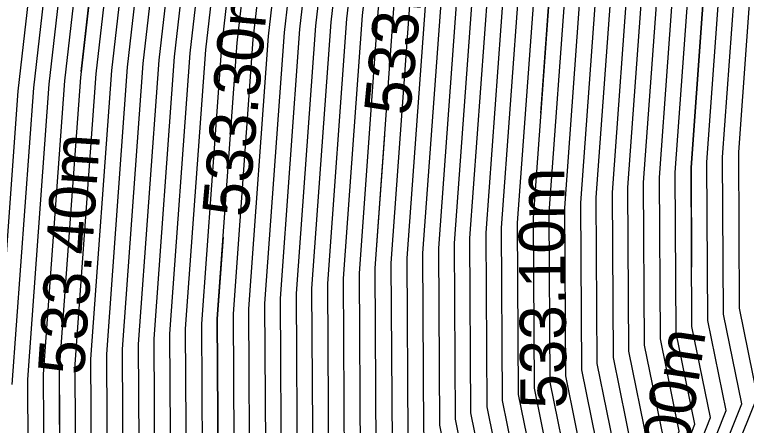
# Model space of a CAD drawing. Extents: x -866683 to -866410, y -1041951 to -1040252.
# Drawn here: x -866449.115 to -866444.371, y -1041933.595 to -1041930.934 of the extents above; entities that cross this region are included whole.
import ezdxf

# ---------------------------------------------------------------- set-up
doc = ezdxf.new("R2010")
doc.units = 0
for name, color, linetype in [('V-HL', 7, 'Continuous'), ('V-VEDL', 7, 'Continuous'), ('V_po_cm', 7, 'Continuous')]:
    doc.layers.add(name, color=color, linetype=linetype)

msp = doc.modelspace()

# ---------------------------------------------------------------- linework, layer by layer
at = {"layer": 'V-HL'}
msp.add_lwpolyline([(-866444.9217, -1041934.3497), (-866444.6048, -1041933.5435), (-866444.724, -1041932.9551), (-866444.7301, -1041931.9234), (-866444.6231, -1041930.4482), (-866444.4031, -1041928.5297), (-866444.4224, -1041928.4411)], dxfattribs=at)
at = {"layer": 'V-VEDL'}
for points in [[(-866449.7169, -1041924.4172), (-866449.1108, -1041924.2576), (-866448.5043, -1041924.4695), (-866447.5946, -1041924.9732), (-866446.3815, -1041925.7685), (-866445.6512, -1041926.9834), (-866445.4039, -1041928.6176), (-866445.6394, -1041930.6714), (-866445.7539, -1041932.2504), (-866445.7474, -1041933.3549), (-866445.6198, -1041933.9847), (-866446.0907, -1041935.3297), (-866447.16, -1041937.39), (-866450.4954, -1041942.9408)], [(-866450.4284, -1041941.6368), (-866447.8087, -1041937.2771), (-866446.9808, -1041935.6001), (-866446.6348, -1041934.426), (-866446.7708, -1041933.7547), (-866446.7777, -1041932.5775), (-866446.6557, -1041930.8945), (-866446.4047, -1041928.7056), (-866446.5506, -1041927.0409), (-866447.0935, -1041925.9004), (-866448.0334, -1041925.2842), (-866448.7383, -1041924.894), (-866449.2081, -1041924.7298), (-866449.6778, -1041924.8534)], [(-866450.3613, -1041940.3327), (-866448.4574, -1041937.1642), (-866447.8709, -1041935.8705), (-866447.6498, -1041934.8672), (-866447.7942, -1041934.1545), (-866447.8016, -1041932.9046), (-866447.672, -1041931.1176), (-866447.4055, -1041928.7935), (-866447.45, -1041927.0984), (-866447.8056, -1041926.0323), (-866448.4722, -1041925.5952), (-866448.9722, -1041925.3184), (-866449.3055, -1041925.2019), (-866449.6386, -1041925.2896)], [(-866449.5994, -1041925.7259), (-866449.4028, -1041925.6741), (-866449.2061, -1041925.7428), (-866448.9111, -1041925.9062), (-866448.5176, -1041926.1641), (-866448.3494, -1041927.1559), (-866448.4062, -1041928.8814), (-866448.6883, -1041931.3407), (-866448.8254, -1041933.2317), (-866448.8176, -1041934.5543), (-866448.6648, -1041935.3085), (-866448.761, -1041936.1408), (-866449.1061, -1041937.0514), (-866450.2943, -1041939.0287)]]:
    msp.add_lwpolyline(points, dxfattribs=at)
at = {"layer": 'V_po_cm'}
for points in [[(-866449.376, -1041923.747), (-866448.9842, -1041923.6438), (-866448.2002, -1041923.9178), (-866447.0241, -1041924.5689), (-866445.4558, -1041925.5971), (-866444.4821, -1041926.9086), (-866444.1029, -1041928.5033), (-866444.3182, -1041930.3813), (-866444.4229, -1041931.8252), (-866444.417, -1041932.8352), (-866444.3003, -1041933.4111), (-866444.9335, -1041934.9782), (-866446.3166, -1041937.5367), (-866448.4496, -1041941.0864), (-866449.9198, -1041942.6695)], [(-866449.9242, -1041942.5721), (-866448.4787, -1041941.0155), (-866446.3815, -1041937.5254), (-866445.0226, -1041935.0053), (-866444.4018, -1041933.4552), (-866444.5193, -1041932.8751), (-866444.5253, -1041931.8579), (-866444.4199, -1041930.4036), (-866444.203, -1041928.5121), (-866444.572, -1041926.9143), (-866445.527, -1041925.6103), (-866447.068, -1041924.6), (-866448.2236, -1041923.9602), (-866448.9939, -1041923.691), (-866449.379, -1041923.7924)], [(-866449.9286, -1041942.4747), (-866448.5078, -1041940.9447), (-866446.4464, -1041937.5141), (-866445.1116, -1041935.0323), (-866444.5033, -1041933.4993), (-866444.6216, -1041932.9151), (-866444.6277, -1041931.8906), (-866444.5215, -1041930.4259), (-866444.303, -1041928.5209), (-866444.6619, -1041926.9201), (-866445.5982, -1041925.6235), (-866447.1119, -1041924.6311), (-866448.247, -1041924.0027), (-866449.0037, -1041923.7382), (-866449.3819, -1041923.8378)], [(-866449.9375, -1041942.2799), (-866448.5659, -1041940.803), (-866446.5761, -1041937.4915), (-866445.2896, -1041935.0864), (-866444.7063, -1041933.5876), (-866444.8263, -1041932.9951), (-866444.8325, -1041931.9561), (-866444.7248, -1041930.4705), (-866444.5032, -1041928.5385), (-866444.8418, -1041926.9316), (-866445.7406, -1041925.6499), (-866447.1996, -1041924.6933), (-866448.2938, -1041924.0876), (-866449.0232, -1041923.8327), (-866449.3877, -1041923.9286)], [(-866449.9419, -1041942.1825), (-866448.595, -1041940.7321), (-866446.641, -1041937.4802), (-866445.3786, -1041935.1134), (-866444.8078, -1041933.6317), (-866444.9287, -1041933.0351), (-866444.9349, -1041931.9888), (-866444.8264, -1041930.4929), (-866444.6033, -1041928.5473), (-866444.9317, -1041926.9374), (-866445.8118, -1041925.6631), (-866447.2435, -1041924.7244), (-866448.3172, -1041924.13), (-866449.0329, -1041923.8799), (-866449.3906, -1041923.9741)], [(-866449.9463, -1041942.0851), (-866448.6241, -1041940.6613), (-866446.7059, -1041937.469), (-866445.4676, -1041935.1405), (-866444.9093, -1041933.6758), (-866445.031, -1041933.075), (-866445.0372, -1041932.0215), (-866444.928, -1041930.5152), (-866444.7033, -1041928.5561), (-866445.0217, -1041926.9431), (-866445.883, -1041925.6762), (-866447.2874, -1041924.7555), (-866448.3406, -1041924.1724), (-866449.0426, -1041923.9271), (-866449.3935, -1041924.0195)], [(-866449.9507, -1041941.9877), (-866448.6532, -1041940.5905), (-866446.7707, -1041937.4577), (-866445.5566, -1041935.1675), (-866445.0108, -1041933.72), (-866445.1333, -1041933.115), (-866445.1396, -1041932.0542), (-866445.0297, -1041930.5375), (-866444.8034, -1041928.5649), (-866445.1116, -1041926.9489), (-866445.9542, -1041925.6894), (-866447.3313, -1041924.7866), (-866448.364, -1041924.2149), (-866449.0524, -1041923.9743), (-866449.3964, -1041924.0649)], [(-866449.3993, -1041924.1103), (-866449.0621, -1041924.0215), (-866448.3874, -1041924.2573), (-866447.3752, -1041924.8177), (-866446.0254, -1041925.7026), (-866445.2016, -1041926.9546), (-866444.9035, -1041928.5737), (-866445.1313, -1041930.5598), (-866445.242, -1041932.0869), (-866445.2357, -1041933.155), (-866445.1123, -1041933.7641), (-866445.6456, -1041935.1945), (-866446.8356, -1041937.4464), (-866448.6823, -1041940.5196), (-866449.9551, -1041941.8903)], [(-866449.9596, -1041941.7928), (-866448.7114, -1041940.4488), (-866446.9005, -1041937.4351), (-866445.7346, -1041935.2216), (-866445.2138, -1041933.8082), (-866445.338, -1041933.195), (-866445.3444, -1041932.1196), (-866445.2329, -1041930.5821), (-866445.0036, -1041928.5825), (-866445.2915, -1041926.9604), (-866446.0966, -1041925.7158), (-866447.419, -1041924.8488), (-866448.4108, -1041924.2998), (-866449.0718, -1041924.0688), (-866449.4022, -1041924.1557)], [(-866449.4051, -1041924.2012), (-866449.0816, -1041924.116), (-866448.4342, -1041924.3422), (-866447.4629, -1041924.8799), (-866446.1679, -1041925.729), (-866445.3814, -1041926.9661), (-866445.1037, -1041928.5912), (-866445.3345, -1041930.6044), (-866445.4468, -1041932.1523), (-866445.4404, -1041933.235), (-866445.3153, -1041933.8523), (-866445.8236, -1041935.2486), (-866446.9654, -1041937.4238), (-866448.7404, -1041940.3779), (-866449.964, -1041941.6954)], [(-866449.4109, -1041924.292), (-866449.101, -1041924.2104), (-866448.4809, -1041924.4271), (-866447.5507, -1041924.9421), (-866446.3103, -1041925.7554), (-866445.5613, -1041926.9776), (-866445.3038, -1041928.6088), (-866445.5378, -1041930.649), (-866445.6515, -1041932.2177), (-866445.645, -1041933.3149), (-866445.5183, -1041933.9406), (-866446.0017, -1041935.3027), (-866447.0951, -1041937.4012), (-866448.7986, -1041940.2362), (-866449.9728, -1041941.5006)], [(-866449.9684, -1041941.598), (-866448.7695, -1041940.3071), (-866447.0302, -1041937.4125), (-866445.9127, -1041935.2757), (-866445.4168, -1041933.8965), (-866445.5427, -1041933.2749), (-866445.5492, -1041932.185), (-866445.4362, -1041930.6267), (-866445.2037, -1041928.6), (-866445.4714, -1041926.9719), (-866446.2391, -1041925.7422), (-866447.5068, -1041924.911), (-866448.4576, -1041924.3847), (-866449.0913, -1041924.1632), (-866449.408, -1041924.2466)], [(-866449.1205, -1041924.3048), (-866448.5277, -1041924.512), (-866447.6385, -1041925.0043), (-866446.4527, -1041925.7817), (-866445.7412, -1041926.9891), (-866445.504, -1041928.6264), (-866445.7411, -1041930.6937), (-866445.8563, -1041932.2832), (-866445.8497, -1041933.3949), (-866445.7213, -1041934.0288), (-866446.1797, -1041935.3568), (-866447.2248, -1041937.3787), (-866448.8568, -1041940.0945), (-866449.9816, -1041941.3058)], [(-866449.9861, -1041941.2084), (-866448.8859, -1041940.0237), (-866447.2897, -1041937.3674), (-866446.2687, -1041935.3838), (-866445.8228, -1041934.073), (-866445.9521, -1041933.4349), (-866445.9587, -1041932.3159), (-866445.8427, -1041930.716), (-866445.6041, -1041928.6352), (-866445.8311, -1041926.9949), (-866446.5239, -1041925.7949), (-866447.6823, -1041925.0354), (-866448.5511, -1041924.5544), (-866449.1302, -1041924.352)], [(-866449.14, -1041924.3993), (-866448.5745, -1041924.5969), (-866447.7262, -1041925.0665), (-866446.5951, -1041925.8081), (-866445.9211, -1041927.0006), (-866445.7041, -1041928.644), (-866445.9443, -1041930.7383), (-866446.0611, -1041932.3486), (-866446.0544, -1041933.4748), (-866445.9243, -1041934.1171), (-866446.3577, -1041935.4108), (-866447.3546, -1041937.3561), (-866448.9149, -1041939.9529), (-866449.9905, -1041941.111)], [(-866449.9949, -1041941.0136), (-866448.944, -1041939.882), (-866447.4195, -1041937.3448), (-866446.4467, -1041935.4379), (-866446.0258, -1041934.1612), (-866446.1567, -1041933.5148), (-866446.1634, -1041932.3813), (-866446.0459, -1041930.7606), (-866445.8042, -1041928.6528), (-866446.011, -1041927.0064), (-866446.6663, -1041925.8213), (-866447.7701, -1041925.0976), (-866448.5979, -1041924.6393), (-866449.1497, -1041924.4465)], [(-866449.1594, -1041924.4937), (-866448.6213, -1041924.6818), (-866447.814, -1041925.1287), (-866446.7375, -1041925.8345), (-866446.1009, -1041927.0121), (-866445.9043, -1041928.6616), (-866446.1476, -1041930.7829), (-866446.2658, -1041932.414), (-866446.2591, -1041933.5548), (-866446.1273, -1041934.2053), (-866446.5357, -1041935.4649), (-866447.4843, -1041937.3335), (-866448.9731, -1041939.8112), (-866449.9993, -1041940.9162)], [(-866449.1692, -1041924.5409), (-866448.6447, -1041924.7242), (-866447.8579, -1041925.1598), (-866446.8087, -1041925.8477), (-866446.1909, -1041927.0179), (-866446.0044, -1041928.6704), (-866446.2492, -1041930.8052), (-866446.3682, -1041932.4467), (-866446.3614, -1041933.5948), (-866446.2288, -1041934.2495), (-866446.6247, -1041935.492), (-866447.5492, -1041937.3222), (-866449.0022, -1041939.7403), (-866450.0037, -1041940.8188)], [(-866449.1789, -1041924.5881), (-866448.6681, -1041924.7666), (-866447.9018, -1041925.1909), (-866446.8799, -1041925.8608), (-866446.2808, -1041927.0236), (-866446.1044, -1041928.6792), (-866446.3508, -1041930.8275), (-866446.4706, -1041932.4794), (-866446.4638, -1041933.6348), (-866446.3303, -1041934.2936), (-866446.7138, -1041935.519), (-866447.6141, -1041937.3109), (-866449.0313, -1041939.6695), (-866450.0081, -1041940.7214)], [(-866449.1886, -1041924.6353), (-866448.6915, -1041924.8091), (-866447.9456, -1041925.222), (-866446.9511, -1041925.874), (-866446.3707, -1041927.0294), (-866446.2045, -1041928.688), (-866446.4525, -1041930.8499), (-866446.573, -1041932.5121), (-866446.5661, -1041933.6747), (-866446.4318, -1041934.3377), (-866446.8028, -1041935.546), (-866447.6789, -1041937.2997), (-866449.0604, -1041939.5986), (-866450.0125, -1041940.6239)], [(-866449.1984, -1041924.6826), (-866448.7149, -1041924.8515), (-866447.9895, -1041925.2531), (-866447.0223, -1041925.8872), (-866446.4607, -1041927.0351), (-866446.3046, -1041928.6968), (-866446.5541, -1041930.8722), (-866446.6754, -1041932.5448), (-866446.6684, -1041933.7147), (-866446.5333, -1041934.3818), (-866446.8918, -1041935.5731), (-866447.7438, -1041937.2884), (-866449.0895, -1041939.5278), (-866450.017, -1041940.5265)], [(-866449.1476, -1041939.3861), (-866447.8736, -1041937.2658), (-866447.0698, -1041935.6271), (-866446.7363, -1041934.4701), (-866446.8731, -1041933.7947), (-866446.8801, -1041932.6102), (-866446.7573, -1041930.9168), (-866446.5048, -1041928.7143), (-866446.6406, -1041927.0466), (-866447.1647, -1041925.9136), (-866448.0773, -1041925.3153), (-866448.7617, -1041924.9364), (-866449.2179, -1041924.777)], [(-866449.1767, -1041939.3152), (-866447.9384, -1041937.2545), (-866447.1588, -1041935.6542), (-866446.8378, -1041934.5142), (-866446.9755, -1041933.8347), (-866446.9825, -1041932.6429), (-866446.859, -1041930.9391), (-866446.6048, -1041928.7231), (-866446.7305, -1041927.0524), (-866447.2359, -1041925.9268), (-866448.1212, -1041925.3464), (-866448.7851, -1041924.9789), (-866449.2276, -1041924.8242)], [(-866449.2058, -1041939.2444), (-866448.0033, -1041937.2432), (-866447.2478, -1041935.6812), (-866446.9393, -1041934.5583), (-866447.0778, -1041933.8746), (-866447.0849, -1041932.6757), (-866446.9606, -1041930.9614), (-866446.7049, -1041928.7319), (-866446.8204, -1041927.0581), (-866447.3071, -1041925.94), (-866448.1651, -1041925.3775), (-866448.8085, -1041925.0213), (-866449.2373, -1041924.8714)], [(-866449.2349, -1041939.1736), (-866448.0682, -1041937.2319), (-866447.3368, -1041935.7082), (-866447.0408, -1041934.6025), (-866447.1801, -1041933.9146), (-866447.1873, -1041932.7084), (-866447.0622, -1041930.9837), (-866446.805, -1041928.7407), (-866446.9104, -1041927.0639), (-866447.3783, -1041925.9531), (-866448.2089, -1041925.4086), (-866448.8318, -1041925.0637), (-866449.2471, -1041924.9186)], [(-866449.2568, -1041924.9659), (-866448.8552, -1041925.1062), (-866448.2528, -1041925.4397), (-866447.4496, -1041925.9663), (-866447.0003, -1041927.0696), (-866446.9051, -1041928.7495), (-866447.1639, -1041931.0061), (-866447.2897, -1041932.7411), (-866447.2825, -1041933.9546), (-866447.1423, -1041934.6466), (-866447.4258, -1041935.7353), (-866448.133, -1041937.2207), (-866449.264, -1041939.1027)], [(-866449.293, -1041939.0319), (-866448.1979, -1041937.2094), (-866447.5148, -1041935.7623), (-866447.2438, -1041934.6907), (-866447.3848, -1041933.9946), (-866447.392, -1041932.7738), (-866447.2655, -1041931.0284), (-866447.0051, -1041928.7583), (-866447.0902, -1041927.0754), (-866447.5208, -1041925.9795), (-866448.2967, -1041925.4708), (-866448.8786, -1041925.1486), (-866449.2665, -1041925.0131)], [(-866449.2763, -1041925.0603), (-866448.902, -1041925.1911), (-866448.3406, -1041925.5019), (-866447.592, -1041925.9927), (-866447.1802, -1041927.0811), (-866447.1052, -1041928.7671), (-866447.3671, -1041931.0507), (-866447.4944, -1041932.8065), (-866447.4872, -1041934.0345), (-866447.3453, -1041934.7348), (-866447.6039, -1041935.7894), (-866448.2628, -1041937.1981), (-866449.3221, -1041938.961)], [(-866449.3512, -1041938.8902), (-866448.3277, -1041937.1868), (-866447.6929, -1041935.8164), (-866447.4468, -1041934.779), (-866447.5895, -1041934.0745), (-866447.5968, -1041932.8392), (-866447.4687, -1041931.073), (-866447.2053, -1041928.7759), (-866447.2701, -1041927.0869), (-866447.6632, -1041926.0059), (-866448.3845, -1041925.533), (-866448.9254, -1041925.2335), (-866449.286, -1041925.1075)], [(-866449.2957, -1041925.1547), (-866448.9488, -1041925.276), (-866448.4284, -1041925.5641), (-866447.7344, -1041926.0191), (-866447.3601, -1041927.0926), (-866447.3054, -1041928.7847), (-866447.5704, -1041931.0953), (-866447.6992, -1041932.8719), (-866447.6918, -1041934.1145), (-866447.5483, -1041934.8231), (-866447.7819, -1041935.8434), (-866448.3925, -1041937.1755), (-866449.3803, -1041938.8193)], [(-866449.3152, -1041925.2491), (-866448.9956, -1041925.3608), (-866448.5161, -1041925.6263), (-866447.8768, -1041926.0454), (-866447.5399, -1041927.1041), (-866447.5055, -1041928.8023), (-866447.7736, -1041931.1399), (-866447.904, -1041932.9373), (-866447.8965, -1041934.1945), (-866447.7513, -1041934.9114), (-866447.9599, -1041935.8975), (-866448.5223, -1041937.1529), (-866449.4385, -1041938.6776)], [(-866449.4675, -1041938.6068), (-866448.5872, -1041937.1417), (-866448.0489, -1041935.9245), (-866447.8528, -1041934.9555), (-866447.9989, -1041934.2344), (-866448.0063, -1041932.97), (-866447.8753, -1041931.1622), (-866447.6056, -1041928.8111), (-866447.6299, -1041927.1099), (-866447.948, -1041926.0586), (-866448.56, -1041925.6574), (-866449.019, -1041925.4033), (-866449.3249, -1041925.2964)], [(-866449.4966, -1041938.5359), (-866448.652, -1041937.1304), (-866448.1379, -1041935.9516), (-866447.9543, -1041934.9996), (-866448.1012, -1041934.2744), (-866448.1087, -1041933.0027), (-866447.9769, -1041931.1846), (-866447.7057, -1041928.8199), (-866447.7198, -1041927.1156), (-866448.0192, -1041926.0718), (-866448.6039, -1041925.6885), (-866449.0424, -1041925.4457), (-866449.3347, -1041925.3436)], [(-866449.5257, -1041938.4651), (-866448.7169, -1041937.1191), (-866448.2269, -1041935.9786), (-866448.0558, -1041935.0437), (-866448.2035, -1041934.3144), (-866448.2111, -1041933.0355), (-866448.0785, -1041931.2069), (-866447.8058, -1041928.8287), (-866447.8097, -1041927.1214), (-866448.0904, -1041926.085), (-866448.6478, -1041925.7196), (-866449.0658, -1041925.4882), (-866449.3444, -1041925.3908)], [(-866449.3541, -1041925.438), (-866449.0892, -1041925.5306), (-866448.6917, -1041925.7507), (-866448.1616, -1041926.0982), (-866447.8997, -1041927.1271), (-866447.9059, -1041928.8374), (-866448.1801, -1041931.2292), (-866448.3135, -1041933.0682), (-866448.3059, -1041934.3544), (-866448.1573, -1041935.0879), (-866448.3159, -1041936.0057), (-866448.7818, -1041937.1078), (-866449.5548, -1041938.3943)], [(-866449.5839, -1041938.3234), (-866448.8466, -1041937.0965), (-866448.405, -1041936.0327), (-866448.2588, -1041935.132), (-866448.4082, -1041934.3944), (-866448.4159, -1041933.1009), (-866448.2818, -1041931.2515), (-866448.0059, -1041928.8462), (-866447.9896, -1041927.1329), (-866448.2328, -1041926.1114), (-866448.7355, -1041925.7818), (-866449.1126, -1041925.5731), (-866449.3639, -1041925.4852)], [(-866449.613, -1041938.2526), (-866448.9115, -1041937.0852), (-866448.494, -1041936.0597), (-866448.3603, -1041935.1761), (-866448.5106, -1041934.4343), (-866448.5183, -1041933.1336), (-866448.3834, -1041931.2738), (-866448.106, -1041928.855), (-866448.0795, -1041927.1386), (-866448.304, -1041926.1246), (-866448.7794, -1041925.8129), (-866449.136, -1041925.6155)], [(-866449.642, -1041938.1817), (-866448.9764, -1041937.0739), (-866448.583, -1041936.0868), (-866448.4618, -1041935.2202), (-866448.6129, -1041934.4743), (-866448.6206, -1041933.1663), (-866448.485, -1041931.2961), (-866448.2061, -1041928.8638), (-866448.1695, -1041927.1444), (-866448.3752, -1041926.1377), (-866448.8233, -1041925.844), (-866449.1594, -1041925.6579)], [(-866449.6711, -1041938.1109), (-866449.0413, -1041937.0626), (-866448.672, -1041936.1138), (-866448.5633, -1041935.2644), (-866448.7152, -1041934.5143), (-866448.723, -1041933.199), (-866448.5867, -1041931.3184), (-866448.3062, -1041928.8726), (-866448.2594, -1041927.1501), (-866448.4464, -1041926.1509), (-866448.8672, -1041925.8751), (-866449.1827, -1041925.7004)], [(-866449.171, -1041937.0401), (-866448.85, -1041936.1679), (-866448.7663, -1041935.3526), (-866448.9199, -1041934.5943), (-866448.9278, -1041933.2644), (-866448.7899, -1041931.3631), (-866448.5063, -1041928.8902), (-866448.4393, -1041927.1616), (-866448.5888, -1041926.1773), (-866448.955, -1041925.9373), (-866449.2295, -1041925.7853)], [(-866449.2763, -1041925.8702), (-866449.0427, -1041925.9995), (-866448.7313, -1041926.2037), (-866448.6192, -1041927.1731), (-866448.7065, -1041928.9078), (-866448.9932, -1041931.4077), (-866449.1325, -1041933.3298)], [(-866449.2359, -1041937.0288), (-866448.939, -1041936.1949), (-866448.8678, -1041935.3967), (-866449.0223, -1041934.6342), (-866449.0302, -1041933.2971), (-866448.8915, -1041931.3854), (-866448.6064, -1041928.899), (-866448.5292, -1041927.1674), (-866448.6601, -1041926.1905), (-866448.9988, -1041925.9684), (-866449.2529, -1041925.8277)], [(-866449.2997, -1041925.9126), (-866449.0866, -1041926.0306), (-866448.8025, -1041926.2169), (-866448.7091, -1041927.1789), (-866448.8066, -1041928.9166), (-866449.0948, -1041931.43), (-866449.2349, -1041933.3625)], [(-866448.6839, -1041931.3027), (-866448.4062, -1041928.8814), (-866448.3539, -1041927.2924)], [(-866445.7048, -1041931.5729), (-866445.6394, -1041930.6714), (-866445.4039, -1041928.6176), (-866445.5828, -1041927.4354)], [(-866444.422, -1041928.4429), (-866444.4031, -1041928.5297), (-866444.6231, -1041930.4482), (-866444.7301, -1041931.9234), (-866444.7263, -1041932.5699)], [(-866447.0896, -1041935.8205), (-866446.9808, -1041935.6001), (-866446.6348, -1041934.426), (-866446.7708, -1041933.7547), (-866446.7777, -1041932.5775), (-866446.715, -1041931.7124)], [(-866447.7632, -1041932.3755), (-866447.8016, -1041932.9046), (-866447.7942, -1041934.1545), (-866447.6498, -1041934.8672), (-866447.8709, -1041935.8705), (-866448.1446, -1041936.4742)], [(-866449.1627, -1041937.1454), (-866449.1061, -1041937.0514), (-866448.761, -1041936.1408), (-866448.6648, -1041935.3085), (-866448.8176, -1041934.5543), (-866448.8244, -1041933.398)]]:
    msp.add_lwpolyline(points, dxfattribs=at)

# ---------------------------------------------------------------- texts
for s, rotation, p in [('533.20m', 84.3928, (-866446.5526, -1041931.5927)), ('533.30m', 84.896, (-866447.6014, -1041932.2504)), ('533.40m', 86.1642, (-866448.6657, -1041933.2734)), ('533.10m', 90.5882, (-866445.5353, -1041933.4853)), ('533.00m', 81.5089, (-866444.8639, -1041934.5361))]:
    msp.add_text(s, height=0.3, rotation=rotation, dxfattribs=at).set_placement(p)

doc.saveas('drawing.dxf')
